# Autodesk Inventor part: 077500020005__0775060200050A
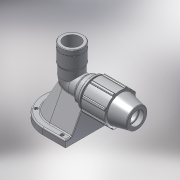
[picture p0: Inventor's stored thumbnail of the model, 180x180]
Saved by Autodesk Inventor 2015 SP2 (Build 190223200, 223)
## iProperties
Created: 2017-02
Part Number: 077500020005__0775060200050A
Material: PVC-Piping
Description: PLASSON WALL PLATE ELBOW 20-1/2"
Document SubType Name: Modeling
Designer: KIM
Mass: 92.6774 g
Surface Area: 199.44 cm^2
Volume: 66.1981 cm^3
Density: 1.4 g/cm^3
Appearance: Smooth - White
Author: KIM
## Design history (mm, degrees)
derived "07750.ipt"
feature "Solid1::07750.ipt"
feature "Solid2::07750.ipt"
tag "TaggingFeature1"
body "Solid1"
other parameters: "d4" = 6.5, "d5" = 19.5, "d7" = 48, "d9" = 11.14286, "d11" = 2.6, "d13" = 120 deg, "d15" = 12 deg, "d16" = 41.76, "d18" = 1, "d19" = 35 deg, "d20" = 17.5 deg, "d21" = 44.64, "d23" = 0, "d25" = 360 deg, "d27" = 0.96, "d33" = 0.4, "d42" = 28.86, "d43" = 1.44, "d46" = 0.6, "d51" = 78, "d68" = 2.6, "d76" = 18.631, "d77" = 20.9, "d79" = 7.4524, "d80" = 0.55893, "d83" = 0, "d84" = 0, "d91" = 36, "d93" = 57, "d94" = 18.631, "d95" = 13.0417, "d96" = 6.5, "d97" = 50 deg, "d98" = 16.7679, "d99" = 0.5, "d100" = 0.5, "d101" = 6.33333, "d112" = 19, "d113" = 26.0834, "d114" = 24.2203, "d115" = -38, "d116" = 7.6, "d118" = 7.6, "d119" = 0, "d120" = 0, "d121" = 90 deg, "d122" = 0, "d123" = 90 deg, "d124" = 1.56, "d126" = 7.6, "d127" = 0, "d128" = 1.52, "d129" = 1.52, "d130" = 6.08, "d131" = 0, "d132" = 1.56, "d133" = 0.78, "d134" = 4, "d135" = 7.8, "d136" = 4, "d137" = 3.9, "d138" = 49.92, "d139" = 15.6, "d141" = 0, "E_" = 48, "A_" = 78, "l_" = 57, "l_1" = 19, "Rp_" = 18.631, "A_2" = 38
